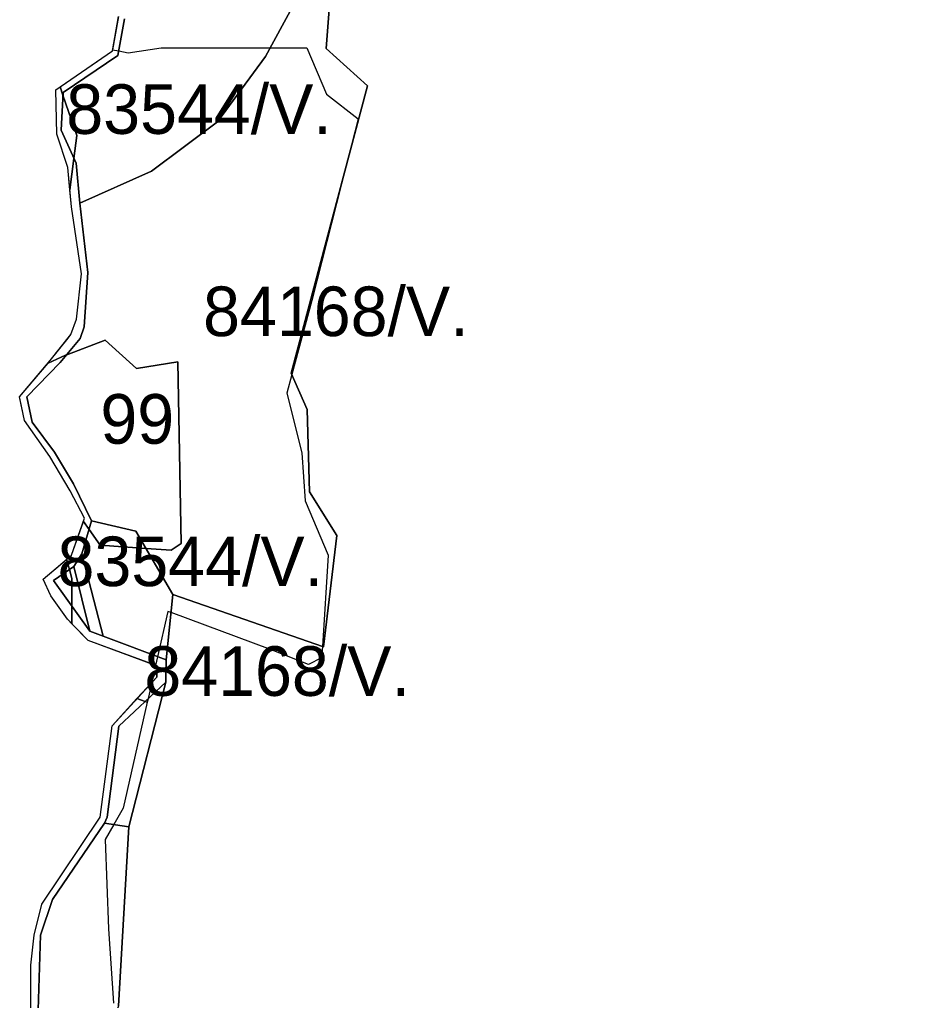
# Model space of a CAD drawing. Extents: x -477304 to -465429, y -1159113 to -1149210.
# Drawn here: x -476271.3 to -476001.7, y -1153991.1 to -1153694.5 of the extents above; entities that cross this region are included whole.
import ezdxf

# ---------------------------------------------------------------- set-up
doc = ezdxf.new("R2010")
doc.units = 0
for name, color, linetype in [('BPEJ_s', 7, 'Continuous'), ('ostatni_s', 7, 'Continuous'), ('PUPFL_s', 7, 'Continuous'), ('voda_s', 7, 'Continuous')]:
    doc.layers.add(name, color=color, linetype=linetype)

msp = doc.modelspace()

# ---------------------------------------------------------------- linework, layer by layer
at = {"layer": 'BPEJ_s'}
for points in [[(-476241.45, -1153693.6), (-476243.23, -1153703.64), (-476241.36, -1153703.98), (-476238.5, -1153704.5), (-476228.5, -1153703), (-476195.54, -1153703), (-476184.5, -1153703), (-476178.5, -1153717), (-476169, -1153724.5), (-476174, -1153744.13), (-476183, -1153779.5), (-476188.98, -1153801.84), (-476190.5, -1153807.5), (-476186, -1153825.5), (-476185, -1153840), (-476178, -1153856.5), (-476179.78, -1153884.14), (-476180, -1153887.5), (-476184, -1153889.5), (-476195.5, -1153885), (-476225.55, -1153873.85), (-476226.5, -1153873.5), (-476229.61, -1153887.2), (-476230.21, -1153889.83), (-476229.75, -1153890), (-476229.85, -1153893.33), (-476231.38, -1153895), (-476232.49, -1153899.88), (-476232.58, -1153900.3), (-476232.72, -1153900.93), (-476240, -1153933), (-476242.88, -1153937.97), (-476245.5, -1153942.5), (-476244.5, -1153969.5), (-476243, -1153992)], [(-476267.97, -1153995.89), (-476267.95, -1153980.53), (-476266.98, -1153971.37), (-476264.6, -1153962.05), (-476247.01, -1153935.72), (-476243.39, -1153908.08), (-476235.86, -1153899.88), (-476233.38, -1153900.71), (-476232.72, -1153900.93), (-476240, -1153933), (-476242.88, -1153937.97), (-476245.5, -1153942.5), (-476244.5, -1153969.5), (-476243, -1153992)]]:
    msp.add_lwpolyline(points, dxfattribs=at)
for points in [[(-476184.5, -1153703), (-476178.5, -1153717), (-476169, -1153724.5), (-476174, -1153744.13), (-476183, -1153779.5), (-476188.98, -1153801.84), (-476190.5, -1153807.5), (-476186, -1153825.5), (-476185, -1153840), (-476178, -1153856.5), (-476179.78, -1153884.14), (-476180, -1153887.5), (-476184, -1153889.5), (-476195.5, -1153885), (-476225.55, -1153873.85), (-476226.5, -1153873.5), (-476229.61, -1153887.2), (-476230.21, -1153889.83), (-476250.63, -1153882.24), (-476255.5, -1153877.23), (-476255.5, -1153871.86), (-476255.5, -1153863.5), (-476256.3, -1153860.82), (-476257.2, -1153857.82), (-476257.2, -1153857.81), (-476255.66, -1153856.52), (-476252.04, -1153846.26), (-476250.34, -1153848.7), (-476247, -1153853.5), (-476233.1, -1153854.47), (-476225.5, -1153855), (-476222.5, -1153853), (-476223.5, -1153798), (-476236, -1153800), (-476245.5, -1153791.5), (-476257.06, -1153795.84), (-476257.5, -1153796), (-476262.73, -1153798.38), (-476262.11, -1153797.64), (-476256.66, -1153790.83), (-476255.82, -1153789.78), (-476254.09, -1153785.08), (-476252.59, -1153771.37), (-476255.67, -1153751.15), (-476256.14, -1153745.96), (-476254.91, -1153736.54), (-476254, -1153729.5), (-476258.23, -1153717.36), (-476259.11, -1153714.85), (-476243.28, -1153703.95), (-476243.23, -1153703.64), (-476241.36, -1153703.98), (-476238.5, -1153704.5), (-476228.5, -1153703), (-476195.54, -1153703)], [(-476254.91, -1153736.54), (-476256.14, -1153745.96), (-476256.74, -1153739.27), (-476260.12, -1153729.15), (-476260.43, -1153715.76), (-476259.11, -1153714.85), (-476258.23, -1153717.36), (-476254, -1153729.5)], [(-476252.04, -1153846.26), (-476251.68, -1153845.24), (-476256.07, -1153836.98), (-476262.17, -1153826.66), (-476269.89, -1153815.72), (-476270.88, -1153810.88), (-476271.34, -1153808.63), (-476262.73, -1153798.38), (-476257.5, -1153796), (-476257.06, -1153795.84), (-476245.5, -1153791.5), (-476236, -1153800), (-476223.5, -1153798), (-476222.5, -1153853), (-476225.5, -1153855), (-476233.1, -1153854.47), (-476247, -1153853.5), (-476250.34, -1153848.7)], [(-476255.5, -1153871.86), (-476255.5, -1153877.23), (-476256.86, -1153875.83), (-476261.88, -1153868.81), (-476264.24, -1153863.72), (-476257.2, -1153857.81), (-476257.2, -1153857.82), (-476256.3, -1153860.82), (-476255.5, -1153863.5)], [(-476232.58, -1153900.3), (-476232.72, -1153900.93), (-476233.38, -1153900.71), (-476235.86, -1153899.88), (-476231.38, -1153895), (-476232.49, -1153899.88)]]:
    msp.add_lwpolyline(points, close=True, dxfattribs=at)
at = {"layer": 'ostatni_s'}
for points in [[(-476254.98, -1153859.9), (-476252.55, -1153856.08), (-476246.04, -1153880.97), (-476250.09, -1153879.43)], [(-476245.7, -1153937.58), (-476244.91, -1153935.7), (-476241.36, -1153908.15), (-476227.09, -1153894.85), (-476238.3, -1153938.61)], [(-476245.7, -1153937.58), (-476238.3, -1153938.61), (-476241.39, -1153992.74), (-476242.85, -1153996.68), (-476265.77, -1153994.01), (-476264.99, -1153971.4), (-476261.43, -1153960.6)]]:
    msp.add_lwpolyline(points, close=True, dxfattribs=at)
at = {"layer": 'PUPFL_s'}
for points in [[(-476241.39, -1153992.74), (-476238.3, -1153938.61), (-476227.09, -1153894.85), (-476227.02, -1153888.18), (-476224.98, -1153868.35), (-476179.46, -1153884.25), (-476175.43, -1153850.5), (-476183.68, -1153837.32), (-476184.38, -1153812.39), (-476189.18, -1153801.39), (-476166.14, -1153714.5), (-476178.61, -1153703.23), (-476176.7, -1153678.16), (-476167.46, -1153679.41), (-476152.76, -1153679.98), (-476138.37, -1153670.35), (-476065.7, -1153644.11), (-476034.71, -1153609.09), (-475997.76, -1153576.14)], [(-476185.68, -1153684.75), (-476196.99, -1153705.68), (-476211.47, -1153725.45), (-476231.5, -1153740.34), (-476253.14, -1153750), (-476254.28, -1153737.93), (-476258.82, -1153727.98), (-476258.19, -1153716.55), (-476241.6, -1153705.3), (-476239.62, -1153694.23)]]:
    msp.add_lwpolyline(points, dxfattribs=at)
for points in [[(-476251.85, -1153787.38), (-476250.71, -1153770.96), (-476253.14, -1153750), (-476231.5, -1153740.34), (-476211.47, -1153725.45), (-476196.99, -1153705.68), (-476185.68, -1153684.75), (-476176.7, -1153678.16), (-476178.61, -1153703.23), (-476166.14, -1153714.5), (-476189.18, -1153801.39), (-476184.38, -1153812.39), (-476183.68, -1153837.32), (-476175.43, -1153850.5), (-476179.46, -1153884.25), (-476224.98, -1153868.35), (-476236.19, -1153849.18), (-476249.57, -1153846.12), (-476255.05, -1153834.92), (-476260.76, -1153825.33), (-476267.59, -1153816.27), (-476269.12, -1153808.64), (-476259.03, -1153798.2), (-476253, -1153790.96)], [(-476249.57, -1153846.12), (-476236.19, -1153849.18), (-476224.98, -1153868.35), (-476227.02, -1153888.18), (-476246.04, -1153880.97), (-476252.55, -1153856.08)], [(-476254.98, -1153859.9), (-476250.09, -1153879.43), (-476261.05, -1153864.1)]]:
    msp.add_lwpolyline(points, close=True, dxfattribs=at)
at = {"layer": 'voda_s'}
for points in [[(-476267.97, -1153995.89), (-476267.95, -1153980.53), (-476266.98, -1153971.37), (-476264.6, -1153962.05), (-476247.01, -1153935.72), (-476243.39, -1153908.08), (-476229.85, -1153893.33), (-476229.75, -1153890), (-476250.63, -1153882.24), (-476256.86, -1153875.83), (-476261.88, -1153868.81), (-476264.24, -1153863.72), (-476255.66, -1153856.52), (-476251.68, -1153845.24), (-476256.07, -1153836.98), (-476262.17, -1153826.66), (-476269.89, -1153815.72), (-476271.34, -1153808.63), (-476262.11, -1153797.64), (-476255.82, -1153789.78), (-476254.09, -1153785.08), (-476252.59, -1153771.37), (-476255.67, -1153751.15), (-476256.74, -1153739.27), (-476260.12, -1153729.15), (-476260.43, -1153715.76), (-476243.28, -1153703.95), (-476241.45, -1153693.6)], [(-476239.62, -1153694.23), (-476241.6, -1153705.3), (-476258.19, -1153716.55), (-476258.82, -1153727.98), (-476254.28, -1153737.93), (-476253.14, -1153750), (-476250.71, -1153770.96), (-476251.85, -1153787.38), (-476253, -1153790.96), (-476259.03, -1153798.2), (-476269.12, -1153808.64), (-476267.59, -1153816.27), (-476260.76, -1153825.33), (-476255.05, -1153834.92), (-476249.57, -1153846.12), (-476252.55, -1153856.08), (-476254.98, -1153859.9), (-476261.05, -1153864.1)], [(-476261.05, -1153864.1), (-476250.09, -1153879.43), (-476246.04, -1153880.97), (-476227.02, -1153888.18), (-476227.09, -1153894.85), (-476241.36, -1153908.15), (-476244.91, -1153935.7), (-476245.7, -1153937.58), (-476261.43, -1153960.6), (-476264.99, -1153971.4), (-476265.77, -1153994.01)]]:
    msp.add_lwpolyline(points, dxfattribs=at)

# ---------------------------------------------------------------- texts
at = {"layer": 'BPEJ_s'}
for s, p in [('83544/V.', (-476257.22, -1153729.06)), ('84168/V.', (-476215.86, -1153790.22)), ('99', (-476246.92, -1153822.77)), ('83544/V.', (-476259.87, -1153865.84)), ('84168/V.', (-476233.62, -1153899.03))]:
    msp.add_text(s, height=15, dxfattribs=at).set_placement(p)

doc.saveas('drawing.dxf')
